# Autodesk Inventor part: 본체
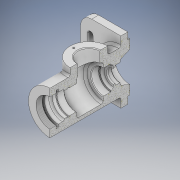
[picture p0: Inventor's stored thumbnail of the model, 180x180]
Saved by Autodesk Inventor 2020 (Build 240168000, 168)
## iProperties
Created: 2021-07
Part Number: 본체
Material: 일반
Document SubType Name: Modeling
Designer: MIRAE
Density: 1 g/cm^3
Appearance: 기본값
Mass: 273.133 g
Surface Area: 646.829 cm^2
Volume: 273.133 cm^3
Author: MIRAE
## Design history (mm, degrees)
sketch "스케치3"
  geometry: L1 (31, -57.5)-(0, -57.5); L2 (0, -57.5)-(0, 57.5); L3 (0, 57.5)-(31, 57.5); L4 (31, 54.5)-(31, -57.5); L5 (16.767, -57.5)-(16.767, -48.5); L6 (16.767, -48.5)-(24, -48.5); L7 (24, -48.5)-(24, -45.5); L8 (24, -45.5)-(20, -45.5); L9 (20, -45.5)-(20, -36.5); L10 (20, -36.5)-(17.5, -36.5); L11 (17.5, -36.5)-(17.5, -31.75); L12 (17.5, -31.75)-(18.5, -31.75); L13 (18.5, -31.75)-(18.5, -30); L14 (18.5, -30)-(17.5, -30); L15 (17.5, -30)-(17.5, -19); L16 (17.5, -19)-(26, -19); L17 (26, -19)-(26, 19); L18 (26, 19)-(17.5, 19); L19 (17.5, 19)-(17.5, 30); L20 (17.5, 30)-(16, 30); L21 (16, 30)-(16, 33.5); L22 (16, 33.5)-(10, 33.5); L23 (10, 33.5)-(10, 36.2); L24 (10, 36.2)-(12.5, 36.2); L25 (12.5, 36.2)-(12.5, 43.5); L26 (12.5, 43.5)-(16, 43.5); L27 (16, 43.5)-(22, 57.5); L28 (31, 57.5)-(35, 57.5); L29 (35, 57.5)-(35, 54.5); L30 (35, 54.5)-(31, 54.5); L31 (31, 54.5)-(31, 57.5); L32 (12.5, 43.5)-(-0.411, 43.5); 4 further points
  constraints: 64 end point, 21 perpendicular, 5 horizontal, 4 parallel, 2 collinear, 2 midpoint, 2 point on line, 1 coincident, 1 horizontal alignment, 1 vertical
  dimensions: "d4" = 115 distance of L3.end L1.start; "d5" = 62 diameter of L4 L2; "d6" = 33.53368 diameter of L5 L2; "d7" = 3 distance of L6.end L7.end; "d8" = 48 diameter of L7 L2; "d9" = 12 distance between parallel lines of L1 L8; "d10" = 21 distance between parallel lines of L1 L10; "d11" = 40 diameter of L9 L2; "d12" = 35 diameter of L11 L2; "d13" = 37 diameter of L13 L2; "d14" = 1.75 distance of L12.end L13.end; "d15" = 11 distance of L14.end L15.end; "d16" = 38 distance of L16.end L17.end; "d17" = 52 diameter of L17 L2; "d18" = 11 distance of L18.end L19.end; "d19" = 32 diameter of L21 L2; "d20" = 91 distance between parallel lines of L1 L22; "d21" = 20 diameter of L23 L2; "d22" = 25 diameter of L25 L2; "d23" = 14 distance between parallel lines of L3 L26; "d24" = 7.3 distance of L24.end L25.end; "d26" = 22 distance of L2.end L27.end; "d27" = 32 diameter of L26.end L2; "d28" = 4 distance of L4.start L29.end; "d29" = 3 distance of L28.end L29.end
revolve "회전1" stored, may be unused: angle "d30" = 90 deg
node "작업 평면1"
sketch "스케치4"
  geometry: L1 (58, -45)-(-58, -45); L2 (-58, -45)-(-58, 45); L3 (-58, 45)-(58, 45); L4 (58, 45)-(58, -45); L5 (58, -45)-(-58, 45); L6 (-58, -45)-(58, 45); 1 further point
  constraints: 12 end point, 2 midpoint, 2 parallel, 1 horizontal, 1 perpendicular
  dimensions: "d40" = 116 distance of L2.end L3.end; "d41" = 90 distance of L1.end L2.end
extrude "돌출2" join sketch "스케치4" distance "d42" = 10; taper "d43" = 0 deg
node "작업 평면3"
sketch "스케치5"
  geometry: L1 (0, -10)-(116, -10) reference; C1 r 27 at (58, -56); 1 further point
  constraints: 1 centre point, 1 vertical alignment
  dimensions: "d46" = 54 diameter of C1; "d47" = 46 distance from line of L1 C1.centre
extrude "돌출3" join sketch "스케치5" stored distance "d48" = 10; taper "d49" = 0 deg
fillet "모깎기1" dims "d50" = 16
sketch "스케치6"
  geometry: L1 (-44, 25)-(-44, -25); L2 (-48, 25)-(-48, -25); L3 (-40, -25)-(-40, 25); L4 (44, 25)-(44, -25); L5 (40, 25)-(40, -25); L6 (48, -25)-(48, 25); A1 r 4 centre (-44, 25) between (-40, 25) and (-48, 25); A2 r 4 centre (-44, -25) between (-48, -25) and (-40, -25); A3 r 4 centre (44, 25) between (48, 25) and (40, 25); A4 r 4 centre (44, -25) between (40, -25) and (48, -25); 3 further points
  constraints: 16 end point, 8 point on circle, 8 tangent, 4 centre point, 2 horizontal alignment, 2 midpoint, 2 parallel, 2 vertical
  dimensions: "d51" = 50 distance of L1.start L1.end; "d52" = 8 diameter of A2; "d53" = 50 distance of L4.start L4.end; "d54" = 8 diameter of A4; "d55" = 88 distance of point (44, 0) point (-44, 0); "d56" = 44 distance of point (0, 0) point (-44, 0)
extrude "돌출4" cut sketch "스케치6" extent not by distance; stored distance "d57" = 0; taper "d58" = 0 deg
revolve "회전2" stored, may be unused: angle "d60" = 360 deg
fillet "모깎기3" dims "d61" = 3
chamfer "모따기1" distance "d62" = 0.7; stored, may be unused: second distance "d63" = 2, angle "d64" = 30 deg
fillet "모깎기4" dims "d65" = 0.3
chamfer "모따기2" distance "d66" = 1; stored, may be unused: second distance "d67" = 2, angle "d68" = 30 deg
fillet "모깎기5" dims "d69" = 3
sketch "스케치7"
  geometry: C1 r 27 at (0, 0) reference; 2 further points
  constraints: 1 coincident
hole "구멍1" sketch "스케치7" at (0, 0) diameter "d70" = 32; stored, may be unused: countersink angle "d74" = 90 deg, drill point angle "d76" = 0 deg; dims "d71" = 6, "d72" = 4, "d73" = 2, "d75" = 8
sketch "스케치8"
  geometry: C1 r 16.767 at (0, 0) reference; 2 further points
  constraints: 1 coincident
hole "구멍2" sketch "스케치8" at (0, 0) diameter "d77" = 40.3762; stored, may be unused: countersink angle "d81" = 90 deg, drill point angle "d83" = 0 deg; dims "d78" = 9, "d79" = 4, "d80" = 2, "d82" = 9
sketch "스케치9"
  geometry: L1 (0, 0)-(22, 0); L2 (0, 0)-(-22, 0); C1 r 16 at (0, 0) reference; A1 r 22 centre (0, 0) between (22, 0) and (-22, 0); 2 further points
  constraints: 4 end point, 3 coincident, 2 horizontal, 2 point on circle, 1 centre point
  dimensions: "d87" = 44 diameter of A1
hole "구멍3" sketch "스케치9" at (-22, 0), (22, 0) diameter "d88" = 2.459; stored, may be unused: countersink angle "d92" = 90 deg, drill point angle "d94" = 118 deg; dims "d89" = 6, "d90" = 4, "d91" = 2, "d93" = 8
node "작업 평면4"
sketch "스케치10"
  geometry: L1 (-37.002, -20.739)-(-37.002, 20.739); L2 (-37.002, 20.739)-(-30.998, 20.739); L3 (-30.998, 20.739)-(-30.998, -20.739); L4 (-30.998, -20.739)-(-37.002, -20.739); L5 (-37.002, -20.739)-(-30.998, 20.739); L6 (-42, -27)-(-42, 27) reference; 3 further points
  constraints: 2 end point, 2 midpoint, 1 horizontal alignment, 2 other
  dimensions: "d95" = 8 distance from line of L6 point (-34, 0)
feature "엠보싱1" sketch "스케치10" dims "d6" = 33.53368, "d96" = 0.5, "d97" = 0
chamfer "모따기4" distance "d98" = 1; stored, may be unused: second distance "d99" = 2, angle "d100" = 30 deg
fillet "모깎기6" dims "d101" = 3
chamfer "모따기5" distance "d102" = 1; stored, may be unused: second distance "d103" = 2, angle "d104" = 30 deg
node "솔리드2"
feature "A9D066F2-1C7D-4E18-AEED-F7BC21143FA4" dims "d77" = 40.3762, "d78" = 9, "d79" = 4, "d80" = 2, "d81" = 90 deg, "d82" = 9, "d83" = 0
other parameters: "d31" = -3, "d45" = -87
